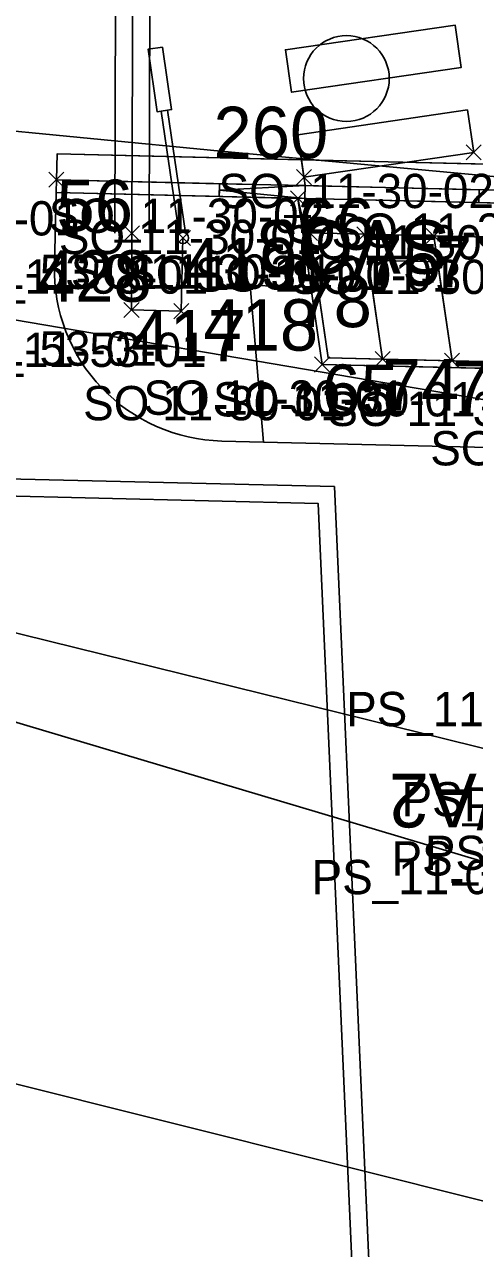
# Model space of a CAD drawing. Extents: x -728800 to -728100, y -1073200 to -1072700.
# Drawn here: x -728521.18 to -728515.93, y -1073041.57 to -1073027.29 of the extents above; entities that cross this region are included whole.
import ezdxf

# ---------------------------------------------------------------- set-up
doc = ezdxf.new("R2010")
doc.units = 0
for name, color, linetype in [('_NOR-návrh tenká', 7, 'Continuous'), ('_NOR-návrh tenká obec', 7, 'Continuous'), ('_NOR-VDZ', 7, 'Continuous'), ('_NOR-šraf_+12', 7, 'Continuous'), ('_NOR-šraf_+6', 7, 'Continuous'), ('_NOR-šraf_bezbariéra', 7, 'Continuous'), ('_NOR-šraf_chodník', 7, 'Continuous'), ('_NOR-šraf_signální pás', 7, 'Continuous'), ('_NOR-šraf_varovný pás', 7, 'Continuous'), ('_NOR-šraf_vozovka', 7, 'Continuous'), ('_NOR-šraf_zeleň', 7, 'Continuous'), ('A1_OBVOD Spravy železnic', 7, 'Continuous'), ('A2_OBVOD STAVBY', 7, 'Continuous'), ('B1_body_poloha', 7, 'Continuous'), ('B2_body_číslo', 7, 'Continuous'), ('B3_body_popiska', 7, 'Continuous'), ('B6_JŽM', 7, 'Continuous'), ('KOS_kabelová trasa VO', 7, 'Continuous'), ('KOS_nové prvky PZZ', 7, 'Continuous'), ('KOS_nové prvky VO', 7, 'Continuous'), ('ZA_02_Dočasný_do_1_roku', 7, 'Continuous'), ('ZZZ_popisky', 7, 'Continuous')]:
    doc.layers.add(name, color=color, linetype=linetype)

msp = doc.modelspace()

# ---------------------------------------------------------------- linework, layer by layer
at = {"layer": '_NOR-návrh tenká'}
for p, q in [((-728520.806, -1073029.105), (-728520.81, -1073029.255)), ((-728518.907, -1073029.3), (-728518.904, -1073029.151)), ((-728517.904, -1073029.174), (-728518.905, -1073029.225)), ((-728517.904, -1073029.174), (-728517.908, -1073029.324)), ((-728518.905, -1073029.225), (-728517.908, -1073029.324)), ((-728517.989, -1073029.322), (-728517.875, -1073029.825)), ((-728517.875, -1073029.825), (-728517.908, -1073029.324)), ((-728517.002, -1073031.196), (-728517.215, -1073029.741)), ((-728516.191, -1073031.215), (-728516.404, -1073029.76)), ((-728517.835, -1073029.819), (-728517.914, -1073029.831))]:
    msp.add_line(p, q, dxfattribs=at)
for points in [[(-728520.806, -1073029.105), (-728520.799, -1073028.805), (-728511.304, -1073029.031), (-728510.067, -1073035.777)], [(-728520.806, -1073029.105), (-728514.808, -1073029.248)], [(-728520.81, -1073029.255), (-728514.811, -1073029.398)], [(-728514.857, -1073031.327), (-728517.706, -1073031.26), (-728517.989, -1073029.322)], [(-728514.855, -1073031.247), (-728517.636, -1073031.181), (-728517.908, -1073029.324)], [(-728517.849, -1073029.726), (-728515.288, -1073029.787)]]:
    msp.add_lwpolyline(points, dxfattribs=at)
at = {"layer": '_NOR-návrh tenká obec'}
for p, q in [((-728518.135, -1073027.59), (-728516.156, -1073027.301)), ((-728516.084, -1073027.796), (-728516.156, -1073027.301)), ((-728518.063, -1073028.085), (-728518.135, -1073027.59)), ((-728518.063, -1073028.085), (-728516.084, -1073027.796)), ((-728517.991, -1073028.58), (-728516.012, -1073028.291)), ((-728515.939, -1073028.786), (-728516.012, -1073028.291)), ((-728517.919, -1073029.075), (-728517.991, -1073028.58)), ((-728517.919, -1073029.075), (-728515.939, -1073028.786))]:
    msp.add_line(p, q, dxfattribs=at)
at = {"layer": '_NOR-VDZ'}
for p, q in [((-728518.135, -1073027.59), (-728516.156, -1073027.301)), ((-728516.084, -1073027.796), (-728516.156, -1073027.301)), ((-728518.063, -1073028.085), (-728518.135, -1073027.59)), ((-728518.063, -1073028.085), (-728516.084, -1073027.796)), ((-728517.991, -1073028.58), (-728516.012, -1073028.291)), ((-728515.939, -1073028.786), (-728516.012, -1073028.291)), ((-728517.919, -1073029.075), (-728517.991, -1073028.58)), ((-728517.919, -1073029.075), (-728515.939, -1073028.786))]:
    msp.add_line(p, q, dxfattribs=at)
for points in [[(-728518.063, -1073028.085), (-728516.084, -1073027.796), (-728516.156, -1073027.301), (-728518.135, -1073027.59), (-728518.063, -1073028.085), (-728518.063, -1073028.085)], [(-728517.919, -1073029.075), (-728515.939, -1073028.786), (-728516.012, -1073028.291), (-728517.991, -1073028.58), (-728517.919, -1073029.075), (-728517.919, -1073029.075)]]:
    msp.add_lwpolyline(points, dxfattribs=at)
at = {"layer": '_NOR-šraf_+12'}
msp.add_lwpolyline([(-728520.81, -1073029.255), (-728518.907, -1073029.3), (-728518.905, -1073029.225), (-728518.904, -1073029.151), (-728520.806, -1073029.105), (-728520.81, -1073029.255)], dxfattribs=at)
at = {"layer": '_NOR-šraf_+6'}
for p, q in [((-728517.875, -1073029.825), (-728517.989, -1073029.322)), ((-728517.989, -1073029.322), (-728517.706, -1073031.26)), ((-728517.908, -1073029.324), (-728517.875, -1073029.825)), ((-728517.849, -1073029.726), (-728517.908, -1073029.324)), ((-728517.835, -1073029.819), (-728517.849, -1073029.726)), ((-728517.636, -1073031.181), (-728517.835, -1073029.819)), ((-728517.002, -1073031.196), (-728517.636, -1073031.181)), ((-728516.191, -1073031.215), (-728517.002, -1073031.196)), ((-728517.706, -1073031.26), (-728514.857, -1073031.327)), ((-728514.855, -1073031.247), (-728516.191, -1073031.215))]:
    msp.add_line(p, q, dxfattribs=at)
at = {"layer": '_NOR-šraf_bezbariéra'}
msp.add_lwpolyline([(-728517.904, -1073029.174), (-728515.876, -1073029.222), (-728515.879, -1073029.372), (-728517.908, -1073029.324), (-728517.904, -1073029.174), (-728517.904, -1073029.174)], dxfattribs=at)
at = {"layer": '_NOR-šraf_chodník'}
for points in [[(-728517.636, -1073031.181), (-728517.002, -1073031.196), (-728517.215, -1073029.741), (-728517.849, -1073029.726), (-728517.835, -1073029.819), (-728517.636, -1073031.181)], [(-728515.288, -1073029.787), (-728516.404, -1073029.76), (-728516.191, -1073031.215), (-728514.855, -1073031.247)]]:
    msp.add_lwpolyline(points, dxfattribs=at)
at = {"layer": '_NOR-šraf_signální pás'}
for p, q in [((-728516.36, -1073030.061), (-728517.171, -1073030.042)), ((-728517.171, -1073030.042), (-728517.002, -1073031.196)), ((-728516.191, -1073031.215), (-728516.36, -1073030.061)), ((-728517.002, -1073031.196), (-728516.191, -1073031.215))]:
    msp.add_line(p, q, dxfattribs=at)
msp.add_lwpolyline([(-728516.36, -1073030.061), (-728516.404, -1073029.76), (-728517.215, -1073029.741), (-728517.171, -1073030.042), (-728516.36, -1073030.061)], dxfattribs=at)
at = {"layer": '_NOR-šraf_varovný pás'}
msp.add_lwpolyline([(-728517.849, -1073029.726), (-728517.215, -1073029.741), (-728516.404, -1073029.76), (-728515.288, -1073029.787), (-728515.347, -1073029.385), (-728515.879, -1073029.372), (-728517.908, -1073029.324), (-728517.849, -1073029.726)], dxfattribs=at)
at = {"layer": '_NOR-šraf_vozovka'}
for points in [[(-728517.948, -1073028.873), (-728517.904, -1073029.174), (-728518.904, -1073029.151), (-728520.806, -1073029.105), (-728520.799, -1073028.805), (-728517.948, -1073028.873)], [(-728515.876, -1073029.222), (-728517.904, -1073029.174), (-728517.948, -1073028.873), (-728515.92, -1073028.921)]]:
    msp.add_lwpolyline(points, dxfattribs=at)
at = {"layer": '_NOR-šraf_zeleň'}
for p, q in [((-728517.838, -1073030.354), (-728518.545, -1073030.338)), ((-728518.545, -1073030.338), (-728518.39, -1073032.164)), ((-728517.706, -1073031.26), (-728517.838, -1073030.354)), ((-728514.857, -1073031.327), (-728517.706, -1073031.26)), ((-728518.39, -1073032.164), (-728514.879, -1073032.247))]:
    msp.add_line(p, q, dxfattribs=at)
msp.add_lwpolyline([(-728518.878, -1073032.152), (-728518.39, -1073032.164), (-728518.545, -1073030.338), (-728517.838, -1073030.354), (-728517.989, -1073029.322), (-728518.907, -1073029.3), (-728520.81, -1073029.255), (-728520.83, -1073030.105), (-728520.83, -1073030.105)], dxfattribs=at)
msp.add_arc((-728518.83, -1073030.153), 2, 178.6393, 268.6393, dxfattribs=at)
at = {"layer": 'A1_OBVOD Spravy železnic'}
msp.add_lwpolyline([(-728582.13, -1073004.22), (-728564.68, -1073020.02), (-728543.86, -1073026.9), (-728510.71, -1073032.54), (-728510.22, -1073036.28), (-728509.415, -1073042.185), (-728509.9, -1073046.86), (-728541.12, -1073039.22), (-728572.55, -1073027.78)], dxfattribs=at)
at = {"layer": 'A2_OBVOD STAVBY'}
msp.add_lwpolyline([(-728564.164, -1073015.523), (-728556.425, -1073019.431), (-728548.14, -1073022.833), (-728542.882, -1073024.621), (-728538.694, -1073025.349), (-728534.14, -1073025.737), (-728532.664, -1073025.787), (-728522.232, -1073025.806), (-728521.488, -1073028.32), (-728521.545, -1073030.726), (-728521.594, -1073032.788), (-728517.755, -1073032.879), (-728517.209, -1073045.129)], dxfattribs=at)
at = {"layer": 'B1_body_poloha'}
for p, q in [((-728516.027, -1073028.698), (-728515.851, -1073028.874)), ((-728516.027, -1073028.874), (-728515.851, -1073028.698)), ((-728520.894, -1073029.017), (-728520.718, -1073029.193)), ((-728520.894, -1073029.193), (-728520.718, -1073029.017)), ((-728518.007, -1073028.987), (-728517.831, -1073029.163)), ((-728518.007, -1073029.163), (-728517.831, -1073028.987)), ((-728518.077, -1073029.234), (-728517.9, -1073029.411)), ((-728518.077, -1073029.411), (-728517.9, -1073029.234)), ((-728520.015, -1073029.642), (-728519.839, -1073029.818)), ((-728520.015, -1073029.818), (-728519.839, -1073029.642)), ((-728517.937, -1073029.637), (-728517.761, -1073029.814)), ((-728517.937, -1073029.814), (-728517.761, -1073029.637)), ((-728519.419, -1073029.696), (-728519.242, -1073029.873)), ((-728519.419, -1073029.873), (-728519.242, -1073029.696)), ((-728517.303, -1073029.653), (-728517.127, -1073029.829)), ((-728517.303, -1073029.829), (-728517.127, -1073029.653)), ((-728516.492, -1073029.672), (-728516.316, -1073029.848)), ((-728516.492, -1073029.848), (-728516.316, -1073029.672)), ((-728520.019, -1073030.536), (-728519.843, -1073030.712)), ((-728520.019, -1073030.712), (-728519.843, -1073030.536)), ((-728519.438, -1073030.55), (-728519.262, -1073030.726)), ((-728519.438, -1073030.726), (-728519.262, -1073030.55)), ((-728517.794, -1073031.172), (-728517.618, -1073031.348)), ((-728517.794, -1073031.348), (-728517.618, -1073031.172)), ((-728517.09, -1073031.108), (-728516.914, -1073031.284)), ((-728517.09, -1073031.284), (-728516.914, -1073031.108)), ((-728516.279, -1073031.127), (-728516.103, -1073031.303)), ((-728516.279, -1073031.303), (-728516.103, -1073031.127))]:
    msp.add_line(p, q, dxfattribs=at)
at = {"layer": 'B2_body_číslo'}
for p, q in [((-728519.738, -1073027.584), (-728519.738, -1073027.584)), ((-728519.57, -1073027.559), (-728519.57, -1073027.559)), ((-728519.632, -1073028.312), (-728519.632, -1073028.312)), ((-728519.463, -1073028.288), (-728519.463, -1073028.288)), ((-728515.939, -1073028.786), (-728515.939, -1073028.786)), ((-728520.806, -1073029.105), (-728520.806, -1073029.105)), ((-728517.919, -1073029.075), (-728517.919, -1073029.075)), ((-728517.989, -1073029.322), (-728517.989, -1073029.322)), ((-728519.927, -1073029.73), (-728519.927, -1073029.73)), ((-728519.331, -1073029.784), (-728519.331, -1073029.784)), ((-728517.849, -1073029.726), (-728517.849, -1073029.726)), ((-728517.215, -1073029.741), (-728517.215, -1073029.741)), ((-728516.404, -1073029.76), (-728516.404, -1073029.76)), ((-728519.931, -1073030.624), (-728519.931, -1073030.624)), ((-728519.35, -1073030.638), (-728519.35, -1073030.638)), ((-728517.002, -1073031.196), (-728517.002, -1073031.196)), ((-728517.706, -1073031.26), (-728517.706, -1073031.26)), ((-728516.191, -1073031.215), (-728516.191, -1073031.215))]:
    msp.add_line(p, q, dxfattribs=at)
at = {"layer": 'B6_JŽM'}
for points in [[(-728300.809, -1073024.355), (-728320.8, -1073026.914), (-728374.008, -1073033.722), (-728429.095, -1073040.747), (-728461.932, -1073044.273), (-728481.199, -1073044.815), (-728499.353, -1073043.648), (-728506.01, -1073042.737), (-728514.574, -1073041.329), (-728535.848, -1073035.998), (-728561.353, -1073026.113), (-728583.963, -1073013.524), (-728603.757, -1072998.891), (-728619.185, -1072984.418), (-728634.193, -1072966.825), (-728646.078, -1072949.194), (-728656.182, -1072930.072), (-728664.987, -1072910.227), (-728668.627, -1072901.808), (-728681.252, -1072876.016), (-728691.886, -1072859.663)], [(-728510.066, -1073037.464), (-728511.097, -1073030.537), (-728511.871, -1073029.55), (-728512.902, -1073029.227), (-728513.865, -1073029.238), (-728518.889, -1073028.771), (-728523.455, -1073028.329), (-728528.834, -1073028.159)], [(-728528.416, -1073033.302), (-728514.713, -1073037.388), (-728514.509, -1073035.909)]]:
    msp.add_lwpolyline(points, dxfattribs=at)
msp.add_circle((-728517.424, -1073027.925), 0.5, dxfattribs=at)
at = {"layer": 'KOS_kabelová trasa VO'}
for p, q in [((-728520.126, -1073029.729), (-728520.105, -1073024.204)), ((-728519.726, -1073029.73), (-728519.705, -1073024.205))]:
    msp.add_line(p, q, dxfattribs=at)
msp.add_lwpolyline([(-728519.905, -1073023.659), (-728519.931, -1073030.624), (-728519.35, -1073030.638), (-728519.331, -1073029.784)], dxfattribs=at)
at = {"layer": 'KOS_nové prvky VO'}
for p, q in [((-728519.376, -1073029.736), (-728519.585, -1073028.306)), ((-728519.301, -1073029.725), (-728519.51, -1073028.295))]:
    msp.add_line(p, q, dxfattribs=at)
msp.add_lwpolyline([(-728519.632, -1073028.312), (-728519.738, -1073027.584), (-728519.57, -1073027.56), (-728519.463, -1073028.288)], close=True, dxfattribs=at)
msp.add_lwpolyline([(-728519.463, -1073028.288), (-728519.57, -1073027.56), (-728519.738, -1073027.584), (-728519.632, -1073028.312), (-728519.463, -1073028.288)], dxfattribs=at)
msp.add_circle((-728519.331, -1073029.784), 0.0665, dxfattribs=at)
at = {"layer": 'ZA_02_Dočasný_do_1_roku'}
msp.add_lwpolyline([(-728517.01, -1073045.12), (-728517.286, -1073038.902), (-728517.563, -1073032.683), (-728521.389, -1073032.592), (-728521.287, -1073028.294), (-728522.083, -1073025.607), (-728532.66, -1073025.587), (-728536.398, -1073025.344), (-728538.668, -1073025.15), (-728542.832, -1073024.426)], dxfattribs=at)
at = {"layer": 'ZZZ_popisky'}
msp.add_lwpolyline([(-728513.758, -1073036.245), (-728529.905, -1073032.263), (-728530.691, -1073035.449)], dxfattribs=at)

# ---------------------------------------------------------------- texts
at = {"layer": 'B2_body_číslo'}
for s, p in [('260', (-728518.974, -1073028.854)), ('56', (-728520.806, -1073029.705)), ('66', (-728517.989, -1073029.922)), ('419', (-728519.331, -1073030.384)), ('75', (-728517.215, -1073030.341)), ('77', (-728516.404, -1073030.36)), ('428', (-728521.033, -1073030.528)), ('78', (-728518.019, -1073030.824)), ('418', (-728519.092, -1073031.098)), ('417', (-728519.931, -1073031.224)), ('74', (-728517.002, -1073031.796)), ('76', (-728516.191, -1073031.815)), ('65', (-728517.706, -1073031.86))]:
    msp.add_text(s, height=0.6, dxfattribs=at).set_placement(p)
at = {"layer": 'B3_body_popiska'}
for s, p in [('SO_11-30-02', (-728518.915, -1073029.436)), ('SO 11-30-01', (-728523.595, -1073029.755)), ('SO_11-30-02', (-728520.895, -1073029.725)), ('SO 11-30-01', (-728517.597, -1073029.898)), ('SO 11-30-01', (-728520.778, -1073029.972)), ('SO 11-30-01', (-728518.136, -1073030.035)), ('SO_11-53-01', (-728522.843, -1073030.38)), ('SO_11-53-01', (-728522.247, -1073030.434)), ('SO 11-30-01', (-728520.638, -1073030.376)), ('SO 11-30-01', (-728520.004, -1073030.391)), ('SO 11-30-01', (-728519.193, -1073030.41)), ('SO 11-30-01', (-728518.077, -1073030.437)), ('SO_11-53-01', (-728522.847, -1073031.274)), ('SO_11-53-01', (-728522.266, -1073031.288)), ('SO 11-30-01', (-728519.791, -1073031.846)), ('SO 11-30-01', (-728518.98, -1073031.865)), ('SO 11-30-01', (-728520.495, -1073031.91)), ('SO 11-30-01', (-728517.646, -1073031.977)), ('SO 11-30-01', (-728516.445, -1073032.436)), ('PS_11-01-31', (-728517.427, -1073035.477)), ('PS_11-01-31', (-728516.781, -1073036.529)), ('PS_11-01-31', (-728516.053, -1073036.588)), ('PS_11-01-31', (-728516.509, -1073037.154)), ('PS_11-01-31', (-728516.898, -1073037.219)), ('PS_11-01-31', (-728517.83, -1073037.436))]:
    msp.add_text(s, height=0.4, dxfattribs=at).set_placement(p)
at = {"layer": 'KOS_nové prvky PZZ'}
msp.add_text('A1/A2', height=0.625, rotation=180, dxfattribs=at).set_placement((-728514.65, -1073036.032))
at = {"layer": 'KOS_nové prvky VO'}
msp.add_text('SVO3', height=0.625, rotation=180, dxfattribs=at).set_placement((-728516.23, -1073029.576))

doc.saveas('drawing.dxf')
